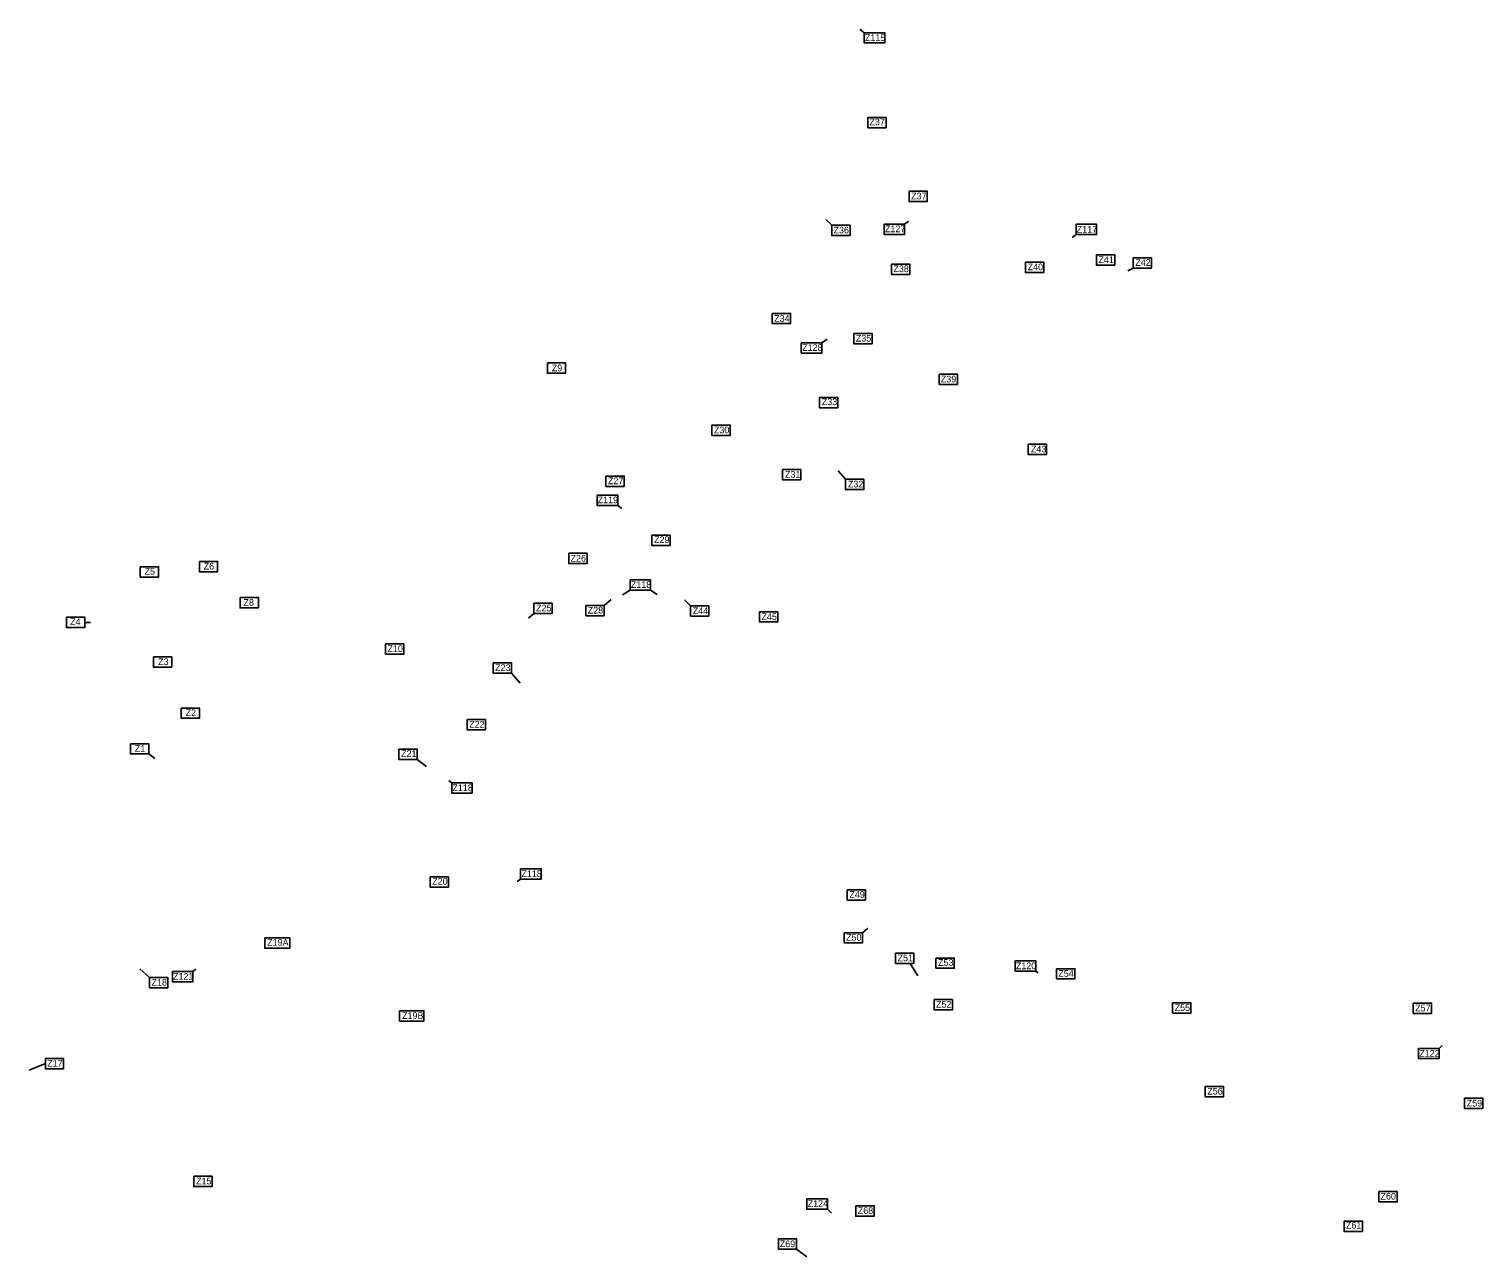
# Model space of a CAD drawing. Extents: x -443483 to -430840, y -1135277 to -1129797.
# Drawn here: x -443031 to -440855, y -1131634 to -1129797 of the extents above; entities that cross this region are included whole.
import ezdxf

# ---------------------------------------------------------------- set-up
doc = ezdxf.new("R2010")
doc.units = 0
doc.layers.add('Vrstva 3', color=7, linetype='Continuous')
doc.layers.add('Vrstva 8', color=7, linetype='Continuous')

msp = doc.modelspace()

# ---------------------------------------------------------------- linework, layer by layer
at = {"layer": 'Vrstva 3'}
for p, q in [((-441780.6, -1129802.1), (-441787.2, -1129796.7)), ((-441829.1, -1130090.3), (-441838, -1130081.7)), ((-441378.1, -1130154.6), (-441386.2, -1130158.4)), ((-441808.5, -1130470.4), (-441819.7, -1130457.7)), ((-442169.8, -1130659.1), (-442159.4, -1130650.4)), ((-442040.6, -1130659.7), (-442049.4, -1130650.9)), ((-442275.3, -1130671.3), (-442283.1, -1130678.3)), ((-442947.3, -1130684.5), (-442938.5, -1130684.6)), ((-442308.6, -1130760.6), (-442295.6, -1130775.5)), ((-442851.5, -1130881.4), (-442842.3, -1130888.4)), ((-442449.5, -1130889.5), (-442435.6, -1130900.4)), ((-441783.2, -1131148.9), (-441775.1, -1131141.9)), ((-441711.9, -1131195), (-441700.6, -1131213.6)), ((-442850.2, -1131215.9), (-442864.6, -1131203.1)), ((-443006.2, -1131344.9), (-443030.6, -1131354.8)), ((-441881.8, -1131622.4), (-441866.7, -1131634.1))]:
    msp.add_line(p, q, dxfattribs=at)
for points in [[(-441780.6, -1129802.1), (-441749.8, -1129802.1), (-441749.8, -1129817.5), (-441780.6, -1129817.5)], [(-441775.4, -1129929), (-441748, -1129929), (-441748, -1129944.4), (-441775.4, -1129944.4)], [(-441713.5, -1130039.3), (-441686.2, -1130039.3), (-441686.2, -1130054.7), (-441713.5, -1130054.7)], [(-441829.1, -1130090.3), (-441801.8, -1130090.3), (-441801.8, -1130105.7), (-441829.1, -1130105.7)], [(-441739.6, -1130148.5), (-441712.2, -1130148.5), (-441712.2, -1130163.9), (-441739.6, -1130163.9)], [(-441539.4, -1130145.7), (-441512, -1130145.7), (-441512, -1130161.1), (-441539.4, -1130161.1)], [(-441433.1, -1130134.4), (-441405.7, -1130134.4), (-441405.7, -1130149.8), (-441433.1, -1130149.8)], [(-441378.1, -1130139.2), (-441350.7, -1130139.2), (-441350.7, -1130154.6), (-441378.1, -1130154.6)], [(-441918.2, -1130222.1), (-441890.9, -1130222.1), (-441890.9, -1130237.5), (-441918.2, -1130237.5)], [(-441796.3, -1130252.1), (-441768.9, -1130252.1), (-441768.9, -1130267.5), (-441796.3, -1130267.5)], [(-442254.8, -1130296.3), (-442227.5, -1130296.3), (-442227.5, -1130311.7), (-442254.8, -1130311.7)], [(-441668.4, -1130313.2), (-441641, -1130313.2), (-441641, -1130328.6), (-441668.4, -1130328.6)], [(-441847.6, -1130348), (-441820.2, -1130348), (-441820.2, -1130363.4), (-441847.6, -1130363.4)], [(-442008.5, -1130389.3), (-441981.2, -1130389.3), (-441981.2, -1130404.7), (-442008.5, -1130404.7)], [(-441535.3, -1130417.8), (-441507.9, -1130417.8), (-441507.9, -1130433.2), (-441535.3, -1130433.2)], [(-441903, -1130455.8), (-441875.6, -1130455.8), (-441875.6, -1130471.2), (-441903, -1130471.2)], [(-442167.1, -1130465.6), (-442139.8, -1130465.6), (-442139.8, -1130481), (-442167.1, -1130481)], [(-441808.5, -1130470.4), (-441781.1, -1130470.4), (-441781.1, -1130485.8), (-441808.5, -1130485.8)], [(-442098.4, -1130554.1), (-442071.1, -1130554.1), (-442071.1, -1130569.5), (-442098.4, -1130569.5)], [(-442222.8, -1130581.2), (-442195.5, -1130581.2), (-442195.5, -1130596.5), (-442222.8, -1130596.5)], [(-442864.1, -1130601.3), (-442836.8, -1130601.3), (-442836.8, -1130616.7), (-442864.1, -1130616.7)], [(-442775.7, -1130593.4), (-442748.3, -1130593.4), (-442748.3, -1130608.8), (-442775.7, -1130608.8)], [(-442714.8, -1130647.5), (-442687.4, -1130647.5), (-442687.4, -1130662.9), (-442714.8, -1130662.9)], [(-442974.7, -1130676.8), (-442947.3, -1130676.8), (-442947.3, -1130692.2), (-442974.7, -1130692.2)], [(-442275.3, -1130655.9), (-442247.9, -1130655.9), (-442247.9, -1130671.3), (-442275.3, -1130671.3)], [(-442197.1, -1130659.1), (-442169.8, -1130659.1), (-442169.8, -1130674.5), (-442197.1, -1130674.5)], [(-442040.6, -1130659.7), (-442013.2, -1130659.7), (-442013.2, -1130675.1), (-442040.6, -1130675.1)], [(-441937.3, -1130668.5), (-441909.9, -1130668.5), (-441909.9, -1130683.9), (-441937.3, -1130683.9)], [(-442497.1, -1130716.5), (-442469.7, -1130716.5), (-442469.7, -1130731.9), (-442497.1, -1130731.9)], [(-442844.2, -1130736.3), (-442816.9, -1130736.3), (-442816.9, -1130751.7), (-442844.2, -1130751.7)], [(-442335.9, -1130745.2), (-442308.6, -1130745.2), (-442308.6, -1130760.6), (-442335.9, -1130760.6)], [(-442802.8, -1130812.7), (-442775.4, -1130812.7), (-442775.4, -1130828.1), (-442802.8, -1130828.1)], [(-442375, -1130829.9), (-442347.6, -1130829.9), (-442347.6, -1130845.3), (-442375, -1130845.3)], [(-442878.9, -1130866.1), (-442851.5, -1130866.1), (-442851.5, -1130881.4), (-442878.9, -1130881.4)], [(-442476.9, -1130874.1), (-442449.5, -1130874.1), (-442449.5, -1130889.5), (-442476.9, -1130889.5)], [(-442430.2, -1131065.5), (-442402.9, -1131065.5), (-442402.9, -1131080.9), (-442430.2, -1131080.9)], [(-441806.3, -1131084.7), (-441778.9, -1131084.7), (-441778.9, -1131100.1), (-441806.3, -1131100.1)], [(-441810.6, -1131148.9), (-441783.2, -1131148.9), (-441783.2, -1131164.3), (-441810.6, -1131164.3)], [(-442677.8, -1131156.7), (-442640.2, -1131156.7), (-442640.2, -1131172.1), (-442677.8, -1131172.1)], [(-441733.7, -1131179.6), (-441706.3, -1131179.6), (-441706.3, -1131195), (-441733.7, -1131195)], [(-441673.2, -1131186.9), (-441645.8, -1131186.9), (-441645.8, -1131202.2), (-441673.2, -1131202.2)], [(-442850.2, -1131215.9), (-442822.9, -1131215.9), (-442822.9, -1131231.3), (-442850.2, -1131231.3)], [(-441492.7, -1131202.8), (-441465.3, -1131202.8), (-441465.3, -1131218.2), (-441492.7, -1131218.2)], [(-441676, -1131249.1), (-441648.6, -1131249.1), (-441648.6, -1131264.5), (-441676, -1131264.5)], [(-441319, -1131254), (-441291.6, -1131254), (-441291.6, -1131269.4), (-441319, -1131269.4)], [(-440958.8, -1131254.3), (-440931.4, -1131254.3), (-440931.4, -1131269.7), (-440958.8, -1131269.7)], [(-442476, -1131265.7), (-442439.7, -1131265.7), (-442439.7, -1131281.1), (-442476, -1131281.1)], [(-443006.2, -1131337.2), (-442978.8, -1131337.2), (-442978.8, -1131352.6), (-443006.2, -1131352.6)], [(-441270.2, -1131379), (-441242.8, -1131379), (-441242.8, -1131394.4), (-441270.2, -1131394.4)], [(-440882, -1131396.5), (-440854.6, -1131396.5), (-440854.6, -1131411.9), (-440882, -1131411.9)], [(-442784.1, -1131513.4), (-442756.7, -1131513.4), (-442756.7, -1131528.8), (-442784.1, -1131528.8)], [(-441010.2, -1131536.4), (-440982.9, -1131536.4), (-440982.9, -1131551.8), (-441010.2, -1131551.8)], [(-441793.2, -1131557.8), (-441765.8, -1131557.8), (-441765.8, -1131573.2), (-441793.2, -1131573.2)], [(-441062.3, -1131580.5), (-441035, -1131580.5), (-441035, -1131595.9), (-441062.3, -1131595.9)], [(-441909.1, -1131607), (-441881.8, -1131607), (-441881.8, -1131622.4), (-441909.1, -1131622.4)]]:
    msp.add_lwpolyline(points, close=True, dxfattribs=at)
at = {"layer": 'Vrstva 8'}
for p, q in [((-441720.1, -1130088.6), (-441714.3, -1130084)), ((-441463.6, -1130104.2), (-441469.4, -1130108.5)), ((-441844, -1130266.2), (-441836.1, -1130260.9)), ((-442149.3, -1130509.6), (-442143.6, -1130514.2)), ((-442131, -1130636.5), (-442142.2, -1130643.1)), ((-442100.3, -1130636.5), (-442090.5, -1130642.7)), ((-442398, -1130924.7), (-442402.3, -1130921.1)), ((-442294.8, -1131068.6), (-442299.8, -1131072.4)), ((-442785.3, -1131206.9), (-442780.8, -1131203.4)), ((-441523.9, -1131206.4), (-441520.2, -1131209.2)), ((-440920.2, -1131322), (-440915.5, -1131317.9)), ((-441835.8, -1131562.7), (-441829.5, -1131568.4))]:
    msp.add_line(p, q, dxfattribs=at)
for points in [[(-441750.9, -1130088.6), (-441720.1, -1130088.6), (-441720.1, -1130104), (-441750.9, -1130104)], [(-441463.6, -1130088.8), (-441432.8, -1130088.8), (-441432.8, -1130104.2), (-441463.6, -1130104.2)], [(-441463.6, -1130088.8), (-441432.8, -1130088.8), (-441432.8, -1130104.2), (-441463.6, -1130104.2)], [(-441874.8, -1130266.2), (-441844, -1130266.2), (-441844, -1130281.6), (-441874.8, -1130281.6)], [(-442180.1, -1130494.2), (-442149.3, -1130494.2), (-442149.3, -1130509.6), (-442180.1, -1130509.6)], [(-442131, -1130621.1), (-442100.3, -1130621.1), (-442100.3, -1130636.5), (-442131, -1130636.5)], [(-442398, -1130924.7), (-442367.2, -1130924.7), (-442367.2, -1130940.1), (-442398, -1130940.1)], [(-442294.8, -1131053.2), (-442264, -1131053.2), (-442264, -1131068.6), (-442294.8, -1131068.6)], [(-441554.7, -1131191), (-441523.9, -1131191), (-441523.9, -1131206.4), (-441554.7, -1131206.4)], [(-442816.1, -1131206.9), (-442785.3, -1131206.9), (-442785.3, -1131222.3), (-442816.1, -1131222.3)], [(-440951, -1131322), (-440920.2, -1131322), (-440920.2, -1131337.4), (-440951, -1131337.4)], [(-441866.6, -1131547.3), (-441835.8, -1131547.3), (-441835.8, -1131562.7), (-441866.6, -1131562.7)]]:
    msp.add_lwpolyline(points, close=True, dxfattribs=at)

# ---------------------------------------------------------------- texts
at = {"layer": 'Vrstva 3'}
for s, p in [('Z115', (-441779.6, -1129814.6)), ('Z37', (-441772.8, -1129940.6)), ('Z37', (-441710.4, -1130051.5)), ('Z36', (-441826.5, -1130102.5)), ('Z38', (-441736.9, -1130160.4)), ('Z40', (-441536, -1130157.5)), ('Z41', (-441430, -1130146.8)), ('Z42', (-441374.9, -1130151)), ('Z34', (-441915.3, -1130234.7)), ('Z35', (-441793.1, -1130264.3)), ('Z9', (-442248.2, -1130308.7)), ('Z39', (-441665.9, -1130325.4)), ('Z33', (-441844.1, -1130359.4)), ('Z30', (-442005.5, -1130401.6)), ('Z43', (-441531.1, -1130430.2)), ('Z31', (-441899.3, -1130468.1)), ('Z27', (-442164.1, -1130477.7)), ('Z32', (-441805, -1130482.6)), ('Z29', (-442095.2, -1130565.8)), ('Z26', (-442220.1, -1130593.6)), ('Z5', (-442857.7, -1130613.2)), ('Z6', (-442769.2, -1130605.4)), ('Z8', (-442709.6, -1130659.7)), ('Z25', (-442271.7, -1130668)), ('Z28', (-442194.4, -1130671.3)), ('Z44', (-442037.3, -1130672.2)), ('Z45', (-441934.4, -1130681)), ('Z4', (-442969.1, -1130688.5)), ('Z10', (-442494.1, -1130728.9)), ('Z3', (-442837.5, -1130748.5)), ('Z23', (-442333, -1130757.3)), ('Z2', (-442796.3, -1130824.6)), ('Z22', (-442371.8, -1130842.1)), ('Z1', (-442872.3, -1130878.1)), ('Z21', (-442473.8, -1130885.9)), ('Z20', (-442427.1, -1131077)), ('Z49', (-441802.8, -1131096.7)), ('Z50', (-441807.7, -1131160.9)), ('Z19A', (-442674.2, -1131168.3)), ('Z51', (-441730.7, -1131191.7)), ('Z53', (-441670.1, -1131198.5)), ('Z18', (-442847.3, -1131228.1)), ('Z54', (-441490.1, -1131214.9)), ('Z52', (-441673.1, -1131261.1)), ('Z55', (-441315.9, -1131266)), ('Z57', (-440956, -1131266.7)), ('Z19B', (-442472.3, -1131277.9)), ('Z17', (-443003.4, -1131349.3)), ('Z56', (-441267.1, -1131391.1)), ('Z59', (-440878.9, -1131409)), ('Z15', (-442780.6, -1131525.6)), ('Z60', (-441007.9, -1131548.3)), ('Z68', (-441790.3, -1131569.8)), ('Z61', (-441059.6, -1131591.7)), ('Z69', (-441907, -1131619.5))]:
    msp.add_text(s, height=10, dxfattribs=at).set_placement(p)
at = {"layer": 'Vrstva 8'}
for s, p in [('Z127', (-441749.5, -1130100.6)), ('Z117', (-441462.5, -1130101.2)), ('Z128', (-441873.4, -1130278.2)), ('Z119', (-442179.6, -1130506.2)), ('Z118', (-442129.9, -1130632.9)), ('Z118', (-442396.9, -1130937.1)), ('Z118', (-442293.7, -1131065.7)), ('Z120', (-441553.6, -1131203.5)), ('Z121', (-442815.1, -1131219.3)), ('Z122', (-440949.9, -1131334.5)), ('Z124', (-441865.2, -1131559.3))]:
    msp.add_text(s, height=10, dxfattribs=at).set_placement(p)

doc.saveas('drawing.dxf')
